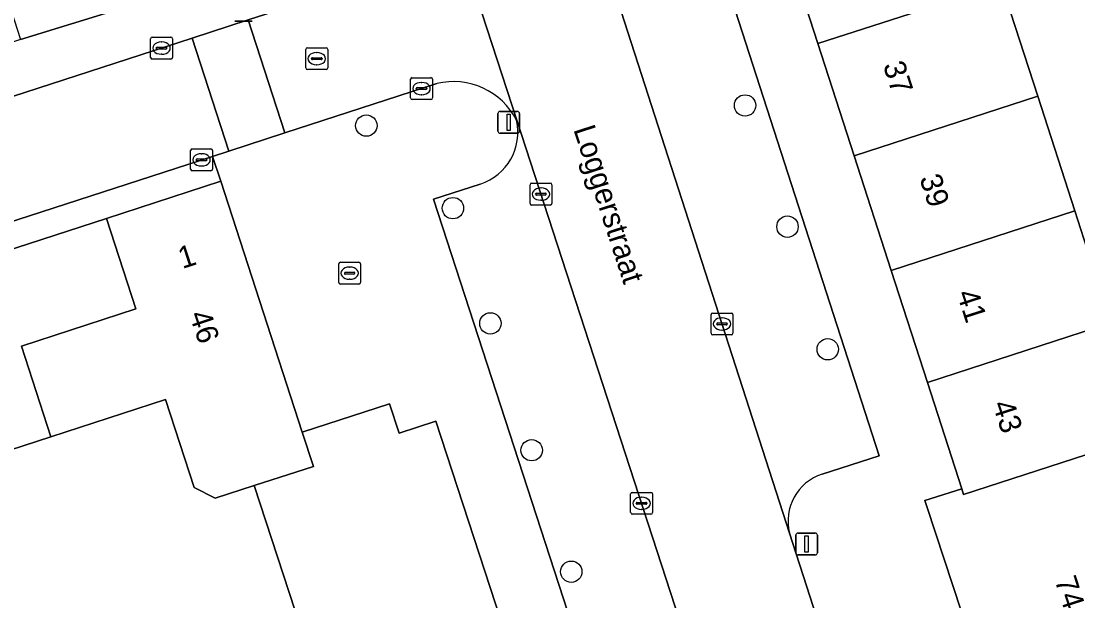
# Model space of a CAD drawing. Extents: x 159371 to 159986, y 382987 to 383597.
# Drawn here: x 159612.86 to 159661.2, y 383131.92 to 383158.46 of the extents above; entities that cross this region are included whole.
import ezdxf

# ---------------------------------------------------------------- set-up
doc = ezdxf.new("R2010")
doc.units = 0
for name, color, linetype in [('IMGEO_Boom', 7, 'Continuous'), ('IMGEO_Erf', 7, 'Continuous'), ('IMGEO_Kolk', 7, 'Continuous'), ('IMGEO_Lichtmast', 7, 'Continuous'), ('IMGEO_Openbare_ruimte_label', 7, 'Continuous'), ('IMGEO_Pand', 7, 'Continuous'), ('IMGEO_Pand_nummerreeks', 7, 'Continuous'), ('IMGEO_Parkeervlak_open', 7, 'Continuous'), ('IMGEO_Rijbaan_lokaal_open', 7, 'Continuous'), ('IMGEO_Rioolput', 7, 'Continuous'), ('IMGEO_Voetpad_open', 7, 'Continuous')]:
    doc.layers.add(name, color=color, linetype=linetype)

msp = doc.modelspace()

# ---------------------------------------------------------------- linework, layer by layer
at = {"layer": 'IMGEO_Boom'}
for centre in [(159645.973, 383154.597), (159628.648, 383153.679), (159632.608, 383149.897), (159647.915, 383149.05), (159634.325, 383144.62), (159649.756, 383143.44), (159636.212, 383138.819), (159638.022, 383133.256)]:
    msp.add_circle(centre, 0.489, dxfattribs=at)
at = {"layer": 'IMGEO_Erf'}
for points in [[(159663.256, 383186.274), (159660.791, 383185.478), (159659.556, 383189.304), (159652.17, 383186.998), (159653.705, 383182.24), (159653.932, 383181.537), (159651.1, 383180.623), (159652.725, 383175.59), (159654.387, 383170.438), (159656.047, 383165.297), (159657.707, 383160.155), (159659.364, 383155.022), (159661.057, 383149.776), (159662.714, 383144.643)], [(159633.655, 383106.186), (159623.518, 383137.198), (159621.739, 383136.62), (159620.77, 383137.114), (159619.462, 383141.14), (159614.222, 383139.438), (159611.675, 383138.61), (159612.436, 383136.265), (159609.59, 383135.341), (159612.499, 383126.378)]]:
    msp.add_lwpolyline(points, dxfattribs=at)
at = {"layer": 'IMGEO_Kolk'}
for p, q in [((159618.78, 383156.798), (159618.78, 383157.65)), ((159618.855, 383157.724), (159619.707, 383157.724)), ((159619.082, 383157.267), (159619.48, 383157.267)), ((159619.268, 383157.504), (159619.293, 383157.504)), ((159619.781, 383157.65), (159619.781, 383156.798)), ((159619.039, 383157.218), (159619.039, 383157.23)), ((159619.477, 383157.181), (159619.079, 383157.181)), ((159619.291, 383156.944), (159619.266, 383156.944)), ((159619.523, 383157.23), (159619.523, 383157.218)), ((159619.707, 383156.724), (159618.855, 383156.724)), ((159630.674, 383154.944), (159630.674, 383155.796)), ((159630.749, 383155.87), (159631.601, 383155.87)), ((159631.675, 383155.796), (159631.675, 383154.944)), ((159630.933, 383155.364), (159630.933, 383155.376)), ((159631.371, 383155.327), (159630.973, 383155.327)), ((159630.976, 383155.413), (159631.374, 383155.413)), ((159631.162, 383155.65), (159631.187, 383155.65)), ((159631.417, 383155.376), (159631.417, 383155.364)), ((159631.601, 383154.87), (159630.749, 383154.87)), ((159631.185, 383155.09), (159631.16, 383155.09)), ((159620.61, 383151.681), (159620.61, 383152.533)), ((159620.685, 383152.607), (159621.537, 383152.607)), ((159621.611, 383152.533), (159621.611, 383151.681)), ((159620.869, 383152.101), (159620.869, 383152.113)), ((159621.307, 383152.064), (159620.909, 383152.064)), ((159620.912, 383152.15), (159621.31, 383152.15)), ((159621.098, 383152.387), (159621.123, 383152.387)), ((159621.353, 383152.113), (159621.353, 383152.101)), ((159621.537, 383151.607), (159620.685, 383151.607)), ((159621.121, 383151.827), (159621.096, 383151.827)), ((159636.136, 383150.115), (159636.136, 383150.967)), ((159636.211, 383151.041), (159637.063, 383151.041)), ((159637.137, 383150.967), (159637.137, 383150.115)), ((159636.395, 383150.535), (159636.395, 383150.547)), ((159636.833, 383150.498), (159636.435, 383150.498)), ((159636.438, 383150.584), (159636.836, 383150.584)), ((159636.624, 383150.821), (159636.649, 383150.821)), ((159636.879, 383150.547), (159636.879, 383150.535)), ((159637.063, 383150.041), (159636.211, 383150.041)), ((159636.647, 383150.261), (159636.622, 383150.261)), ((159627.385, 383146.496), (159627.385, 383147.348)), ((159627.46, 383147.422), (159628.312, 383147.422)), ((159627.873, 383147.202), (159627.898, 383147.202)), ((159628.386, 383147.348), (159628.386, 383146.496)), ((159627.644, 383146.916), (159627.644, 383146.928)), ((159628.082, 383146.879), (159627.684, 383146.879)), ((159627.687, 383146.965), (159628.085, 383146.965)), ((159627.896, 383146.642), (159627.871, 383146.642)), ((159628.128, 383146.928), (159628.128, 383146.916)), ((159628.312, 383146.422), (159627.46, 383146.422)), ((159644.42, 383144.172), (159644.42, 383145.024)), ((159644.495, 383145.098), (159645.347, 383145.098)), ((159644.908, 383144.878), (159644.933, 383144.878)), ((159645.421, 383145.024), (159645.421, 383144.172)), ((159644.679, 383144.592), (159644.679, 383144.604)), ((159645.117, 383144.555), (159644.719, 383144.555)), ((159644.722, 383144.641), (159645.12, 383144.641)), ((159644.931, 383144.318), (159644.906, 383144.318)), ((159645.163, 383144.604), (159645.163, 383144.592)), ((159645.347, 383144.098), (159644.495, 383144.098)), ((159640.741, 383135.962), (159640.741, 383136.814)), ((159640.816, 383136.888), (159641.668, 383136.888)), ((159641.229, 383136.668), (159641.254, 383136.668)), ((159641.742, 383136.814), (159641.742, 383135.962)), ((159641, 383136.382), (159641, 383136.394)), ((159641.438, 383136.345), (159641.04, 383136.345)), ((159641.043, 383136.431), (159641.441, 383136.431)), ((159641.252, 383136.108), (159641.227, 383136.108)), ((159641.484, 383136.394), (159641.484, 383136.382)), ((159641.668, 383135.888), (159640.816, 383135.888))]:
    msp.add_line(p, q, dxfattribs=at)
for points in [[(159618.78, 383156.798), (159618.78, 383157.65)], [(159618.855, 383157.724), (159619.707, 383157.724)], [(159619.781, 383157.65), (159619.781, 383156.798)], [(159619.707, 383156.724), (159618.855, 383156.724)], [(159630.674, 383154.944), (159630.674, 383155.796)], [(159630.749, 383155.87), (159631.601, 383155.87)], [(159631.675, 383155.796), (159631.675, 383154.944)], [(159631.601, 383154.87), (159630.749, 383154.87)], [(159620.61, 383151.681), (159620.61, 383152.533)], [(159620.685, 383152.607), (159621.537, 383152.607)], [(159621.611, 383152.533), (159621.611, 383151.681)], [(159621.537, 383151.607), (159620.685, 383151.607)], [(159636.136, 383150.115), (159636.136, 383150.967)], [(159636.211, 383151.041), (159637.063, 383151.041)], [(159637.137, 383150.967), (159637.137, 383150.115)], [(159637.063, 383150.041), (159636.211, 383150.041)], [(159627.385, 383146.496), (159627.385, 383147.348)], [(159627.46, 383147.422), (159628.312, 383147.422)], [(159628.386, 383147.348), (159628.386, 383146.496)], [(159628.312, 383146.422), (159627.46, 383146.422)], [(159644.42, 383144.172), (159644.42, 383145.024)], [(159644.495, 383145.098), (159645.347, 383145.098)], [(159645.421, 383145.024), (159645.421, 383144.172)], [(159645.347, 383144.098), (159644.495, 383144.098)], [(159640.741, 383135.962), (159640.741, 383136.814)], [(159640.816, 383136.888), (159641.668, 383136.888)], [(159641.742, 383136.814), (159641.742, 383135.962)], [(159641.668, 383135.888), (159640.816, 383135.888)]]:
    msp.add_lwpolyline(points, dxfattribs=at)
for centre, radius, start, end in [((159618.857, 383157.648), 0.0765, 91.552, 178.448), ((159618.857, 383157.648), 0.0765, 91.552, 178.448), ((159619.079, 383157.227), 0.0403, 85.8775, 175.7526), ((159619.484, 383157.229), 0.0386, 1.7309, 96.639), ((159619.705, 383157.648), 0.0765, 1.552, 88.448), ((159619.705, 383157.648), 0.0765, 1.552, 88.448), ((159618.857, 383156.8), 0.0765, 181.552, 268.448), ((159618.857, 383156.8), 0.0765, 181.552, 268.448), ((159619.076, 383157.217), 0.0366, 178.938, 274.7102), ((159619.48, 383157.224), 0.043, 264.8664, 352.4533), ((159619.705, 383156.8), 0.0765, 271.552, 358.448), ((159619.705, 383156.8), 0.0765, 271.552, 358.448), ((159630.751, 383155.794), 0.0765, 91.552, 178.448), ((159630.751, 383155.794), 0.0765, 91.552, 178.448), ((159631.599, 383155.794), 0.0765, 1.552, 88.448), ((159631.599, 383155.794), 0.0765, 1.552, 88.448), ((159630.973, 383155.373), 0.0403, 85.8775, 175.7526), ((159630.97, 383155.363), 0.0366, 178.938, 274.7102), ((159631.374, 383155.37), 0.043, 264.8664, 352.4533), ((159631.378, 383155.375), 0.0386, 1.7309, 96.639), ((159630.751, 383154.946), 0.0765, 181.552, 268.448), ((159630.751, 383154.946), 0.0765, 181.552, 268.448), ((159631.599, 383154.946), 0.0765, 271.552, 358.448), ((159631.599, 383154.946), 0.0765, 271.552, 358.448), ((159620.687, 383152.531), 0.0765, 91.552, 178.448), ((159620.687, 383152.531), 0.0765, 91.552, 178.448), ((159621.535, 383152.531), 0.0765, 1.552, 88.448), ((159621.535, 383152.531), 0.0765, 1.552, 88.448), ((159620.909, 383152.11), 0.0403, 85.8775, 175.7526), ((159620.906, 383152.1), 0.0366, 178.938, 274.7102), ((159621.31, 383152.107), 0.043, 264.8664, 352.4533), ((159621.314, 383152.112), 0.0386, 1.7309, 96.639), ((159620.687, 383151.683), 0.0765, 181.552, 268.448), ((159620.687, 383151.683), 0.0765, 181.552, 268.448), ((159621.535, 383151.683), 0.0765, 271.552, 358.448), ((159621.535, 383151.683), 0.0765, 271.552, 358.448), ((159636.213, 383150.965), 0.0765, 91.552, 178.448), ((159636.213, 383150.965), 0.0765, 91.552, 178.448), ((159637.061, 383150.965), 0.0765, 1.552, 88.448), ((159637.061, 383150.965), 0.0765, 1.552, 88.448), ((159636.435, 383150.544), 0.0403, 85.8775, 175.7526), ((159636.432, 383150.534), 0.0366, 178.938, 274.7102), ((159636.836, 383150.541), 0.043, 264.8664, 352.4533), ((159636.84, 383150.546), 0.0386, 1.7309, 96.639), ((159636.213, 383150.117), 0.0765, 181.552, 268.448), ((159636.213, 383150.117), 0.0765, 181.552, 268.448), ((159637.061, 383150.117), 0.0765, 271.552, 358.448), ((159637.061, 383150.117), 0.0765, 271.552, 358.448), ((159627.462, 383147.346), 0.0765, 91.552, 178.448), ((159627.462, 383147.346), 0.0765, 91.552, 178.448), ((159628.31, 383147.346), 0.0765, 1.552, 88.448), ((159628.31, 383147.346), 0.0765, 1.552, 88.448), ((159627.684, 383146.925), 0.0403, 85.8775, 175.7526), ((159627.681, 383146.915), 0.0366, 178.938, 274.7102), ((159628.085, 383146.922), 0.043, 264.8664, 352.4533), ((159628.089, 383146.927), 0.0386, 1.7309, 96.639), ((159627.462, 383146.498), 0.0765, 181.552, 268.448), ((159627.462, 383146.498), 0.0765, 181.552, 268.448), ((159628.31, 383146.498), 0.0765, 271.552, 358.448), ((159628.31, 383146.498), 0.0765, 271.552, 358.448), ((159644.497, 383145.022), 0.0765, 91.552, 178.448), ((159644.497, 383145.022), 0.0765, 91.552, 178.448), ((159645.345, 383145.022), 0.0765, 1.552, 88.448), ((159645.345, 383145.022), 0.0765, 1.552, 88.448), ((159644.719, 383144.601), 0.0403, 85.8775, 175.7526), ((159644.716, 383144.591), 0.0366, 178.938, 274.7102), ((159645.12, 383144.598), 0.043, 264.8664, 352.4533), ((159645.124, 383144.603), 0.0386, 1.7309, 96.639), ((159644.497, 383144.174), 0.0765, 181.552, 268.448), ((159644.497, 383144.174), 0.0765, 181.552, 268.448), ((159645.345, 383144.174), 0.0765, 271.552, 358.448), ((159645.345, 383144.174), 0.0765, 271.552, 358.448), ((159640.818, 383136.812), 0.0765, 91.552, 178.448), ((159640.818, 383136.812), 0.0765, 91.552, 178.448), ((159641.666, 383136.812), 0.0765, 1.552, 88.448), ((159641.666, 383136.812), 0.0765, 1.552, 88.448), ((159641.04, 383136.391), 0.0403, 85.8775, 175.7526), ((159641.037, 383136.381), 0.0366, 178.938, 274.7102), ((159641.441, 383136.388), 0.043, 264.8664, 352.4533), ((159641.445, 383136.393), 0.0386, 1.7309, 96.639), ((159640.818, 383135.964), 0.0765, 181.552, 268.448), ((159640.818, 383135.964), 0.0765, 181.552, 268.448), ((159641.666, 383135.964), 0.0765, 271.552, 358.448), ((159641.666, 383135.964), 0.0765, 271.552, 358.448)]:
    msp.add_arc(centre, radius, start, end, dxfattribs=at)
for centre, major_axis, ratio, start_param, end_param in [((159619.267, 383157.224), (-0.387, 0.002), 0.722429, 4.712389, 7.853982), ((159619.292, 383157.224), (-0.39, 0.002), 0.717154, 1.570796, 4.712389), ((159631.161, 383155.37), (-0.387, 0.002), 0.722429, 4.712389, 7.853982), ((159631.186, 383155.37), (-0.39, 0.002), 0.717154, 1.570796, 4.712389), ((159621.097, 383152.107), (-0.387, 0.002), 0.722429, 4.712389, 7.853982), ((159621.122, 383152.107), (-0.39, 0.002), 0.717154, 1.570796, 4.712389), ((159636.623, 383150.541), (-0.387, 0.002), 0.722429, 4.712389, 7.853982), ((159636.648, 383150.541), (-0.39, 0.002), 0.717154, 1.570796, 4.712389), ((159627.872, 383146.922), (-0.387, 0.002), 0.722429, 4.712389, 7.853982), ((159627.897, 383146.922), (-0.39, 0.002), 0.717154, 1.570796, 4.712389), ((159644.907, 383144.598), (-0.387, 0.002), 0.722429, 4.712389, 7.853982), ((159644.932, 383144.598), (-0.39, 0.002), 0.717154, 1.570796, 4.712389), ((159641.228, 383136.388), (-0.387, 0.002), 0.722429, 4.712389, 7.853982), ((159641.253, 383136.388), (-0.39, 0.002), 0.717154, 1.570796, 4.712389)]:
    msp.add_ellipse(centre, major_axis=major_axis, ratio=ratio, start_param=start_param, end_param=end_param, dxfattribs=at)
at = {"layer": 'IMGEO_Lichtmast'}
for p, q in [((159623.429, 383158.458), (159622.639, 383158.458)), ((159622.639, 383158.458), (159623.429, 383158.458)), ((159634.666, 383153.428), (159634.666, 383154.228)), ((159634.666, 383154.228), (159634.666, 383153.428)), ((159634.766, 383154.328), (159635.556, 383154.328)), ((159635.556, 383154.328), (159634.766, 383154.328)), ((159635.656, 383154.228), (159635.656, 383153.428)), ((159635.656, 383153.428), (159635.656, 383154.228)), ((159635.556, 383153.328), (159634.766, 383153.328)), ((159634.766, 383153.328), (159635.556, 383153.328)), ((159648.396, 383135.023), (159649.186, 383135.023)), ((159649.186, 383135.023), (159648.396, 383135.023)), ((159648.296, 383134.123), (159648.296, 383134.923)), ((159648.296, 383134.923), (159648.296, 383134.123)), ((159649.286, 383134.923), (159649.286, 383134.123)), ((159649.286, 383134.123), (159649.286, 383134.923)), ((159649.186, 383134.023), (159648.396, 383134.023)), ((159648.396, 383134.023), (159649.186, 383134.023))]:
    msp.add_line(p, q, dxfattribs=at)
for points in [[(159635.086, 383154.203), (159635.236, 383154.203), (159635.236, 383153.453), (159635.086, 383153.453), (159635.086, 383154.203)], [(159648.716, 383134.898), (159648.866, 383134.898), (159648.866, 383134.148), (159648.716, 383134.148), (159648.716, 383134.898)]]:
    msp.add_lwpolyline(points, dxfattribs=at)
for centre, start, end in [((159634.766, 383154.228), 90, 180), ((159634.766, 383154.228), 90, 180), ((159635.556, 383154.228), 0, 90), ((159635.556, 383154.228), 360, 90), ((159634.766, 383153.428), 180, 270), ((159634.766, 383153.428), 180, 270), ((159635.556, 383153.428), 270, 0), ((159635.556, 383153.428), 270, 0), ((159648.396, 383134.923), 90, 180), ((159648.396, 383134.923), 90, 180), ((159649.186, 383134.923), 0, 90), ((159649.186, 383134.923), 360, 90), ((159648.396, 383134.123), 180, 270), ((159648.396, 383134.123), 180, 270), ((159649.186, 383134.123), 270, 0), ((159649.186, 383134.123), 270, 0)]:
    msp.add_arc(centre, 0.1, start, end, dxfattribs=at)
at = {"layer": 'IMGEO_Pand'}
for points in [[(159656.047, 383165.297), (159647.648, 383162.571), (159649.308, 383157.429), (159657.707, 383160.155)], [(159657.707, 383160.155), (159649.308, 383157.429), (159650.965, 383152.296), (159659.364, 383155.022)], [(159652.658, 383147.049), (159661.057, 383149.776), (159659.364, 383155.022), (159650.965, 383152.296)], [(159614.222, 383139.438), (159619.462, 383141.14), (159620.77, 383137.114), (159621.739, 383136.62), (159623.518, 383137.198), (159626.229, 383138.078), (159625.718, 383139.649), (159621.989, 383151.129), (159616.759, 383149.43), (159618.106, 383145.284), (159612.875, 383143.584)], [(159652.658, 383147.049), (159654.315, 383141.917), (159662.714, 383144.643), (159661.057, 383149.776)], [(159614.222, 383139.438), (159612.875, 383143.584), (159618.106, 383145.284), (159616.759, 383149.43), (159606.135, 383145.979), (159607.976, 383140.311), (159608.771, 383137.864), (159609.59, 383135.341), (159612.436, 383136.265), (159611.675, 383138.61)], [(159662.714, 383144.643), (159654.315, 383141.917), (159655.885, 383137.052), (159655.971, 383136.784), (159662.694, 383138.967), (159662.767, 383138.741), (159664.444, 383139.282), (159664.37, 383139.511)], [(159633.655, 383106.186), (159640.321, 383108.351), (159642.026, 383108.904), (159631.823, 383140.148), (159630.152, 383139.605), (159629.716, 383140.948), (159625.718, 383139.649), (159626.229, 383138.078), (159623.518, 383137.198)], [(159662.767, 383138.741), (159662.694, 383138.967), (159655.971, 383136.784), (159655.885, 383137.052), (159654.204, 383136.509), (159654.291, 383136.239), (159659.423, 383120.624), (159667.794, 383123.344), (159666.005, 383128.71)]]:
    msp.add_lwpolyline(points, close=True, dxfattribs=at)
at = {"layer": 'IMGEO_Parkeervlak_open'}
for points in [[(159632.631, 383182.71), (159636.253, 383171.476), (159637.07, 383168.944), (159648.013, 383135.014)], [(159649.5, 383137.722), (159652.102, 383138.561), (159637.995, 383182.3), (159635.392, 383181.461)], [(159650.784, 383107.038), (159649.677, 383110.258), (159645.878, 383122.127), (159635.526, 383153.919)], [(159633.859, 383151.002), (159631.721, 383150.306), (159645.651, 383107.489), (159648.027, 383108.262)]]:
    msp.add_lwpolyline(points, dxfattribs=at)
for centre, radius, start, end in [((159633.086, 383153.379), 2.499, 288.0199, 12.4861), ((159650.189, 383135.581), 2.249, 107.8424, 194.614)]:
    msp.add_arc(centre, radius, start, end, dxfattribs=at)
at = {"layer": 'IMGEO_Rijbaan_lokaal_open'}
for points in [[(159648.013, 383135.014), (159637.07, 383168.944), (159631.239, 383167.064), (159632.049, 383164.565), (159632.113, 383164.417), (159635.526, 383153.919), (159645.878, 383122.127), (159649.677, 383110.258), (159650.784, 383107.038), (159651.919, 383103.426)], [(159635.526, 383153.919), (159632.113, 383164.417), (159632.049, 383164.565)], [(159630.143, 383160.751), (159623.242, 383158.511), (159624.919, 383153.341), (159631.87, 383155.597)], [(159656.864, 383107.752), (159656.807, 383107.935), (159656.745, 383108.164), (159655.403, 383112.312), (159655.14, 383113.126), (159649.868, 383129.251), (159648.013, 383135.014)]]:
    msp.add_lwpolyline(points, dxfattribs=at)
for points in [[(159623.242, 383158.511), (159620.674, 383157.677), (159622.351, 383152.508), (159624.919, 383153.341)], [(159583.074, 383139.761), (159621.616, 383152.269), (159622.351, 383152.508), (159620.674, 383157.677), (159613.632, 383155.391), (159581.397, 383144.927)]]:
    msp.add_lwpolyline(points, close=True, dxfattribs=at)
msp.add_arc((159632.638, 383152.449), 3.24, 26.9765, 103.716, dxfattribs=at)
at = {"layer": 'IMGEO_Rioolput'}
for p, q in [((159625.88, 383156.314), (159625.88, 383157.166)), ((159625.955, 383157.24), (159626.807, 383157.24)), ((159626.182, 383156.783), (159626.58, 383156.783)), ((159626.368, 383157.02), (159626.393, 383157.02)), ((159626.881, 383157.166), (159626.881, 383156.314)), ((159626.139, 383156.734), (159626.139, 383156.746)), ((159626.577, 383156.697), (159626.179, 383156.697)), ((159626.391, 383156.46), (159626.366, 383156.46)), ((159626.623, 383156.746), (159626.623, 383156.734)), ((159626.807, 383156.24), (159625.955, 383156.24))]:
    msp.add_line(p, q, dxfattribs=at)
for points in [[(159625.88, 383156.314), (159625.88, 383157.166)], [(159625.955, 383157.24), (159626.807, 383157.24)], [(159626.881, 383157.166), (159626.881, 383156.314)], [(159626.807, 383156.24), (159625.955, 383156.24)]]:
    msp.add_lwpolyline(points, dxfattribs=at)
for centre, radius, start, end in [((159625.957, 383157.164), 0.0765, 91.552, 178.448), ((159625.957, 383157.164), 0.0765, 91.552, 178.448), ((159626.179, 383156.743), 0.0403, 85.8775, 175.7526), ((159626.584, 383156.745), 0.0386, 1.7309, 96.639), ((159626.805, 383157.164), 0.0765, 1.552, 88.448), ((159626.805, 383157.164), 0.0765, 1.552, 88.448), ((159625.957, 383156.316), 0.0765, 181.552, 268.448), ((159625.957, 383156.316), 0.0765, 181.552, 268.448), ((159626.176, 383156.733), 0.0366, 178.938, 274.7102), ((159626.58, 383156.74), 0.043, 264.8664, 352.4533), ((159626.805, 383156.316), 0.0765, 271.552, 358.448), ((159626.805, 383156.316), 0.0765, 271.552, 358.448)]:
    msp.add_arc(centre, radius, start, end, dxfattribs=at)
for centre, major_axis, ratio, start_param, end_param in [((159626.367, 383156.74), (-0.387, 0.002), 0.722429, 4.712389, 7.853982), ((159626.392, 383156.74), (-0.39, 0.002), 0.717154, 1.570796, 4.712389)]:
    msp.add_ellipse(centre, major_axis=major_axis, ratio=ratio, start_param=start_param, end_param=end_param, dxfattribs=at)
at = {"layer": 'IMGEO_Voetpad_open'}
for points in [[(159594.442, 383213.217), (159595.914, 383209.856), (159597.617, 383204.596), (159599.287, 383199.441), (159600.938, 383194.343), (159602.595, 383189.226), (159604.282, 383184.014), (159605.945, 383178.879), (159607.603, 383173.761), (159609.269, 383168.616), (159610.997, 383163.278), (159612.832, 383157.613), (159617.501, 383159.044)], [(159650.965, 383152.296), (159649.308, 383157.429), (159647.648, 383162.571), (159645.988, 383167.713), (159644.326, 383172.863), (159642.663, 383178.015), (159640.948, 383183.328), (159639.141, 383188.927), (159638.871, 383189.779), (159638.782, 383189.751), (159637.079, 383189.212), (159636.292, 383188.974), (159636.136, 383188.93)], [(159635.392, 383181.461), (159637.995, 383182.3), (159652.102, 383138.561), (159649.5, 383137.722)], [(159629.905, 383163.051), (159624.274, 383161.231), (159621.615, 383160.371), (159619.719, 383159.759), (159619.228, 383159.6), (159617.501, 383159.044), (159612.832, 383157.613), (159610.08, 383156.722), (159607.215, 383155.794), (159605.399, 383161.403), (159602.64, 383160.51), (159588.363, 383155.773), (159586.028, 383154.998), (159584.604, 383154.526), (159586.423, 383148.888), (159581.227, 383147.212), (159576.085, 383145.553), (159570.933, 383143.892), (159565.791, 383142.233), (159560.48, 383140.52), (159558.768, 383140.208)], [(159613.632, 383155.391), (159620.674, 383157.677), (159623.242, 383158.511), (159630.143, 383160.751)], [(159560.645, 383138.19), (159578.781, 383144.078), (159581.397, 383144.927), (159613.632, 383155.391)], [(159631.87, 383155.597), (159624.919, 383153.341), (159622.351, 383152.508), (159621.616, 383152.269), (159621.989, 383151.129), (159625.718, 383139.649), (159629.716, 383140.948), (159630.152, 383139.605), (159631.823, 383140.148), (159642.026, 383108.904), (159640.321, 383108.351), (159644.09, 383096.707), (159651.919, 383103.426), (159650.784, 383107.038)], [(159606.135, 383145.979), (159616.759, 383149.43), (159621.989, 383151.129), (159621.616, 383152.269), (159583.074, 383139.761), (159582.831, 383139.682)], [(159668.043, 383116.911), (159671.247, 383118.076), (159669.201, 383123.801), (159667.794, 383123.344), (159659.423, 383120.624), (159654.291, 383136.239), (159654.204, 383136.509), (159655.885, 383137.052), (159654.315, 383141.917), (159652.658, 383147.049), (159650.965, 383152.296)], [(159648.027, 383108.262), (159645.651, 383107.489), (159631.721, 383150.306), (159633.859, 383151.002)], [(159648.013, 383135.014), (159649.868, 383129.251), (159655.14, 383113.126), (159655.403, 383112.312), (159663.049, 383115.094)]]:
    msp.add_lwpolyline(points, dxfattribs=at)
for centre, radius, start, end in [((159632.638, 383152.449), 3.24, 26.9765, 103.716), ((159633.086, 383153.379), 2.499, 288.0199, 12.4861), ((159650.189, 383135.581), 2.249, 107.8424, 194.614)]:
    msp.add_arc(centre, radius, start, end, dxfattribs=at)

# ---------------------------------------------------------------- texts
at = {"layer": 'IMGEO_Openbare_ruimte_label'}
msp.add_text('Loggerstraat', height=1, rotation=288.0001, dxfattribs=at).set_placement((159638.113, 383153.507))
at = {"layer": 'IMGEO_Pand_nummerreeks'}
for s, rotation, p in [('37', 287.8891, (159652.274, 383156.445)), ('39', 287.8891, (159653.943, 383151.273)), ('1', 17.9967, (159620.234, 383147.11)), ('41', 287.8891, (159655.646, 383145.995)), ('46', 288.4349, (159620.538, 383145.028)), ('43', 287.8875, (159657.282, 383140.93)), ('74-74A', 287.8875, (159660.127, 383132.873))]:
    msp.add_text(s, height=1, rotation=rotation, dxfattribs=at).set_placement(p)

doc.saveas('drawing.dxf')
